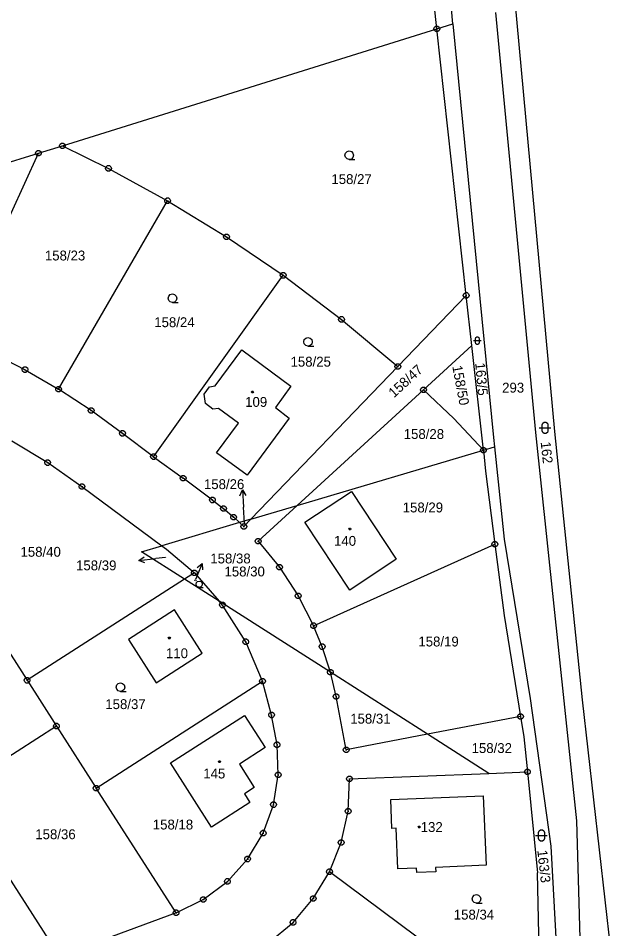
# Model space of a CAD drawing. Extents: x -780000 to -777378, y -1011169 to -1009297.
# Drawn here: x -779316 to -779212.2, y -1010124.6 to -1009967.9 of the extents above; entities that cross this region are included whole.
import ezdxf

# ---------------------------------------------------------------- set-up
doc = ezdxf.new("R2010")
doc.units = 0
for name, color, linetype in [('Default', 7, 'Continuous'), ('KN_HRANICE', 7, 'Continuous'), ('KN_KULTURY', 7, 'Continuous'), ('KN_PARCELY', 7, 'Continuous')]:
    doc.layers.add(name, color=color, linetype=linetype)

# ---------------------------------------------------------------- blocks, each defined once
blk = doc.blocks.new('304')
at = {"layer": 'Default'}
blk.add_lwpolyline([(0, 0), (-0.38, 0.1), (-0.65, 0.37), (-0.75, 0.74), (-0.65, 1.11), (-0.38, 1.38), (-0.01, 1.48), (0.36, 1.38), (0.63, 1.11), (0.73, 0.73), (0.63, 0.35), (0.36, 0.08), (-0.02, -0.02), (0.98, -0.02)], dxfattribs=at)
blk = doc.blocks.new('316')
at = {"layer": 'Default'}
for points in [[(-0.5, 1.5), (-0.4, 1.79), (-0.15, 1.97), (0.16, 1.97), (0.41, 1.79), (0.51, 1.5), (0.51, 0.5), (0.41, 0.21), (0.16, 0.03), (-0.15, 0.03), (-0.4, 0.21), (-0.5, 0.5), (-0.5, 1.5)], [(-1, 1), (0.27, 1), (1, 1)]]:
    blk.add_lwpolyline(points, dxfattribs=at)
blk = doc.blocks.new('10292')
at = {"layer": 'Default'}
blk.add_line((0, 3), (0, 0), dxfattribs=at)
blk.add_lwpolyline([(-0.5, 2), (0, 3), (0.5, 2)], dxfattribs=at)
blk = doc.blocks.new('105')
at = {"layer": 'Default'}
blk.add_line((-0.12, 0), (0.12, 0), dxfattribs=at)
blk.add_lwpolyline([(0.15, 0.48), (0.4, 0.3), (0.5, 0.01), (0.4, -0.28), (0.15, -0.46), (-0.16, -0.46), (-0.41, -0.28), (-0.51, 0.01), (-0.41, 0.3), (-0.16, 0.48), (0.15, 0.48)], dxfattribs=at)
blk = doc.blocks.new('402')
at = {"layer": 'Default'}
blk.add_lwpolyline([(0.09, 0.15), (0.18, 0), (0.09, -0.15), (-0.09, -0.15), (-0.18, 0), (-0.09, 0.15), (0.09, 0.15)], dxfattribs=at)

msp = doc.modelspace()

# ---------------------------------------------------------------- linework, layer by layer
at = {"layer": 'KN_HRANICE'}
for p, q in [((-779241.08, -1009968.91), (-779246.23, -1009913.12)), ((-779234.8, -1009917.25), (-779223.59, -1010039.03)), ((-779243.85, -1009969.77), (-779249.52, -1009918.58)), ((-779226.79, -1010039.25), (-779233.71, -1009966.95)), ((-779243.85, -1009969.77), (-779241.08, -1009968.91)), ((-779241.08, -1009968.91), (-779234.07, -1010040.11)), ((-779308.35, -1009989.9), (-779243.85, -1009969.77)), ((-779238.78, -1010015.64), (-779243.85, -1009969.77)), ((-779340.12, -1009999.61), (-779312.49, -1009991.16)), ((-779326.85, -1010022.6), (-779312.49, -1009991.16)), ((-779312.49, -1009991.16), (-779308.35, -1009989.9)), ((-779308.35, -1009989.9), (-779300.4, -1009993.78)), ((-779300.4, -1009993.78), (-779290.22, -1009999.35)), ((-779309, -1010031.79), (-779290.22, -1009999.35)), ((-779290.22, -1009999.35), (-779280.07, -1010005.56)), ((-779280.07, -1010005.56), (-779270.32, -1010012.18)), ((-779292.64, -1010043.39), (-779270.32, -1010012.18)), ((-779270.32, -1010012.18), (-779260.26, -1010019.77)), ((-779238.78, -1010015.64), (-779250.57, -1010027.88)), ((-779237.83, -1010024.25), (-779238.78, -1010015.64)), ((-779260.26, -1010019.77), (-779250.57, -1010027.88)), ((-779320.74, -1010025.36), (-779314.79, -1010028.42)), ((-779282.06, -1010031.21), (-779277.45, -1010024.98)), ((-779277.45, -1010024.98), (-779268.99, -1010031.25)), ((-779246.15, -1010031.88), (-779237.83, -1010024.25)), ((-779235.83, -1010042.28), (-779237.83, -1010024.25)), ((-779314.79, -1010028.42), (-779309, -1010031.79)), ((-779275.87, -1010054.16), (-779250.57, -1010027.88)), ((-779303.4, -1010035.47), (-779309, -1010031.79)), ((-779283.96, -1010032.63), (-779283.04, -1010031.37)), ((-779283.04, -1010031.37), (-779282.06, -1010031.21)), ((-779268.99, -1010031.25), (-779271.67, -1010034.94)), ((-779246.15, -1010031.88), (-779267.94, -1010051.81)), ((-779240.94, -1010036.84), (-779246.15, -1010031.88)), ((-779283.73, -1010034.23), (-779283.96, -1010032.63)), ((-779282.46, -1010035.19), (-779283.73, -1010034.23)), ((-779281.44, -1010035.08), (-779282.46, -1010035.19)), ((-779278, -1010037.62), (-779281.44, -1010035.08)), ((-779271.67, -1010034.94), (-779269.29, -1010036.77)), ((-779298.01, -1010039.38), (-779303.4, -1010035.47)), ((-779281.78, -1010042.74), (-779278, -1010037.62)), ((-779269.29, -1010036.77), (-779276.53, -1010046.6)), ((-779235.83, -1010042.28), (-779240.94, -1010036.84)), ((-779292.64, -1010043.39), (-779298.01, -1010039.38)), ((-779219.75, -1010106.05), (-779226.79, -1010039.25)), ((-779223.59, -1010039.03), (-779218.82, -1010085.26)), ((-779317.04, -1010040.66), (-779310.89, -1010044.42)), ((-779234.07, -1010040.11), (-779233.9, -1010041.71)), ((-779276.53, -1010046.6), (-779281.78, -1010042.74)), ((-779267.94, -1010051.81), (-779235.83, -1010042.28)), ((-779235.83, -1010042.28), (-779233.9, -1010041.71)), ((-779235.83, -1010042.28), (-779235.48, -1010045.87)), ((-779233.9, -1010041.71), (-779232.26, -1010057.56)), ((-779310.89, -1010044.42), (-779304.98, -1010048.53)), ((-779292.64, -1010043.39), (-779287.56, -1010047.11)), ((-779235.48, -1010045.87), (-779233.85, -1010058.45)), ((-779282.51, -1010050.85), (-779287.56, -1010047.11)), ((-779304.98, -1010048.53), (-779291.21, -1010058.71)), ((-779266.57, -1010054.66), (-779258.57, -1010049.37)), ((-779258.57, -1010049.37), (-779250.85, -1010061.04)), ((-779282.51, -1010050.85), (-779280.61, -1010052.33)), ((-779280.61, -1010052.33), (-779278.85, -1010053.8)), ((-779275.87, -1010054.16), (-779267.94, -1010051.81)), ((-779274.64, -1010057.94), (-779267.94, -1010051.81)), ((-779278.85, -1010053.8), (-779277.83, -1010054.74)), ((-779277.83, -1010054.74), (-779291.21, -1010058.71)), ((-779275.87, -1010054.16), (-779277.83, -1010054.74)), ((-779277.83, -1010054.74), (-779277.09, -1010055.43)), ((-779277.09, -1010055.43), (-779275.87, -1010054.16)), ((-779258.86, -1010066.35), (-779266.57, -1010054.66)), ((-779274.64, -1010057.94), (-779270.95, -1010062.42)), ((-779265.07, -1010072.49), (-779233.85, -1010058.45)), ((-779233.85, -1010058.45), (-779232.26, -1010070.73)), ((-779232.26, -1010057.56), (-779227.75, -1010085.02)), ((-779329.26, -1010058.8), (-779314.44, -1010081.88)), ((-779294.7, -1010059.75), (-779291.21, -1010058.71)), ((-779287.31, -1010064.46), (-779294.7, -1010059.75)), ((-779291.21, -1010058.71), (-779290.44, -1010059.28)), ((-779290.44, -1010059.28), (-779285.62, -1010063.38)), ((-779250.85, -1010061.04), (-779258.86, -1010066.35)), ((-779270.95, -1010062.42), (-779267.73, -1010067.35)), ((-779287.31, -1010064.46), (-779314.44, -1010081.88)), ((-779285.62, -1010063.38), (-779287.31, -1010064.46)), ((-779281.34, -1010068.27), (-779287.31, -1010064.46)), ((-779285.62, -1010063.38), (-779281.34, -1010068.27)), ((-779267.73, -1010067.35), (-779265.07, -1010072.49)), ((-779280.77, -1010068.92), (-779281.34, -1010068.27)), ((-779262.19, -1010080.48), (-779281.34, -1010068.27)), ((-779276.77, -1010075.24), (-779280.77, -1010068.92)), ((-779289.06, -1010069.75), (-779296.99, -1010074.85)), ((-779284.27, -1010077.21), (-779289.06, -1010069.75)), ((-779232.26, -1010070.73), (-779229.43, -1010088.1)), ((-779263.6, -1010076.09), (-779265.07, -1010072.49)), ((-779296.99, -1010074.85), (-779292.21, -1010082.32)), ((-779273.87, -1010082.04), (-779276.77, -1010075.24)), ((-779292.21, -1010082.32), (-779284.27, -1010077.21)), ((-779262.23, -1010080.33), (-779263.6, -1010076.09)), ((-779262.19, -1010080.48), (-779262.23, -1010080.33)), ((-779245.44, -1010091.17), (-779262.19, -1010080.48)), ((-779261.21, -1010084.68), (-779262.19, -1010080.48)), ((-779314.44, -1010081.88), (-779309.39, -1010089.76)), ((-779302.53, -1010100.44), (-779273.87, -1010082.04)), ((-779272.31, -1010087.85), (-779273.87, -1010082.04)), ((-779259.45, -1010093.86), (-779261.21, -1010084.68)), ((-779227.75, -1010085.02), (-779224.22, -1010110.43)), ((-779218.82, -1010085.26), (-779212.16, -1010143.8)), ((-779271.38, -1010092.97), (-779272.31, -1010087.85)), ((-779229.43, -1010088.1), (-779245.44, -1010091.17)), ((-779229.43, -1010088.1), (-779228.86, -1010091.61)), ((-779309.39, -1010089.76), (-779327.06, -1010101.1)), ((-779309.39, -1010089.76), (-779302.53, -1010100.44)), ((-779245.44, -1010091.17), (-779259.45, -1010093.86)), ((-779234.88, -1010097.91), (-779245.44, -1010091.17)), ((-779271.18, -1010098.16), (-779271.38, -1010092.97)), ((-779228.86, -1010091.61), (-779228.25, -1010097.65)), ((-779234.88, -1010097.91), (-779228.25, -1010097.65)), ((-779228.25, -1010097.65), (-779226.51, -1010114.99)), ((-779271.98, -1010103.28), (-779271.18, -1010098.16)), ((-779259.13, -1010104.42), (-779258.88, -1010098.83)), ((-779258.88, -1010098.83), (-779234.88, -1010097.91)), ((-779288.77, -1010121.88), (-779302.53, -1010100.44)), ((-779327.06, -1010101.1), (-779310.76, -1010126.49)), ((-779273.75, -1010108.17), (-779271.98, -1010103.28)), ((-779260.32, -1010109.8), (-779259.13, -1010104.42)), ((-779218.61, -1010144.17), (-779219.75, -1010106.05)), ((-779276.44, -1010112.63), (-779273.75, -1010108.17)), ((-779262.32, -1010114.82), (-779260.32, -1010109.8)), ((-779224.22, -1010110.43), (-779222.02, -1010149.91)), ((-779279.93, -1010116.49), (-779276.44, -1010112.63)), ((-779265.13, -1010119.44), (-779262.32, -1010114.82)), ((-779225.9, -1010141.96), (-779262.32, -1010114.82)), ((-779225.9, -1010141.96), (-779226.51, -1010114.99)), ((-779284.08, -1010119.61), (-779279.93, -1010116.49)), ((-779288.77, -1010121.88), (-779284.08, -1010119.61)), ((-779268.62, -1010123.54), (-779265.13, -1010119.44)), ((-779288.77, -1010121.88), (-779301.33, -1010126.54)), ((-779272.77, -1010127.01), (-779268.62, -1010123.54))]:
    msp.add_line(p, q, dxfattribs=at)
for points in [[(-779289.75, -1010096.1), (-779276.98, -1010087.91), (-779273.41, -1010093.44), (-779277.86, -1010096.28), (-779275.33, -1010100.31), (-779276.97, -1010101.4), (-779276.04, -1010102.9), (-779282.66, -1010107.15)], [(-779235.38, -1010113.69), (-779244.08, -1010114.07), (-779244.05, -1010114.82), (-779247.31, -1010114.94), (-779247.33, -1010114.19), (-779250.56, -1010114.32), (-779250.87, -1010107.34), (-779251.58, -1010107.36), (-779251.76, -1010102.41), (-779235.86, -1010101.78)]]:
    msp.add_lwpolyline(points, close=True, dxfattribs=at)
at = {"layer": 'KN_PARCELY'}
for p, q in [((-779276.99, -1010054.84), (-779277.15, -1010052.08)), ((-779290.6, -1010060.73), (-779292.23, -1010060.91)), ((-779285.55, -1010064.78), (-779285.44, -1010064.52))]:
    msp.add_line(p, q, dxfattribs=at)

# ---------------------------------------------------------------- block references
at = {"layer": 'KN_KULTURY'}
for name, p in [('304', (-779258.94, -1009992.24)), ('304', (-779289.39, -1010016.86)), ('304', (-779266.04, -1010024.35)), ('402', (-779275.61, -1010032.25)), ('316', (-779225.22, -1010039.43)), ('402', (-779258.82, -1010055.84)), ('402', (-779289.94, -1010074.61)), ('304', (-779298.35, -1010083.78)), ('402', (-779281.29, -1010095.89)), ('402', (-779246.89, -1010107.14)), ('316', (-779225.83, -1010109.58)), ('304', (-779237.02, -1010120.23))]:
    msp.add_blockref(name, p, dxfattribs=at)
for name, p, xscale, yscale in [('316', (-779236.88, -1010024.09), 0.67, 0.67), ('304', (-779284.79, -1010065.87), 0.72, 0.72)]:
    msp.add_blockref(name, p, dxfattribs=dict(at, xscale=xscale, yscale=yscale))
at = {"layer": 'KN_PARCELY'}
for p in [(-779243.85, -1009969.77), (-779308.35, -1009989.9), (-779312.49, -1009991.16), (-779300.4, -1009993.78), (-779290.22, -1009999.35), (-779280.07, -1010005.56), (-779270.32, -1010012.18), (-779238.78, -1010015.64), (-779260.26, -1010019.77), (-779314.79, -1010028.42), (-779250.57, -1010027.88), (-779309, -1010031.79), (-779246.15, -1010031.88), (-779303.4, -1010035.47), (-779298.01, -1010039.38), (-779292.64, -1010043.39), (-779235.83, -1010042.28), (-779310.89, -1010044.42), (-779287.56, -1010047.11), (-779304.98, -1010048.53), (-779282.51, -1010050.85), (-779280.61, -1010052.33), (-779278.85, -1010053.8), (-779277.09, -1010055.43), (-779274.64, -1010057.94), (-779233.85, -1010058.45), (-779285.62, -1010063.38), (-779270.95, -1010062.42), (-779267.73, -1010067.35), (-779280.77, -1010068.92), (-779265.07, -1010072.49), (-779276.77, -1010075.24), (-779263.6, -1010076.09), (-779262.19, -1010080.48), (-779314.44, -1010081.88), (-779273.87, -1010082.04), (-779261.21, -1010084.68), (-779272.31, -1010087.85), (-779229.43, -1010088.1), (-779309.39, -1010089.76), (-779271.38, -1010092.97), (-779259.45, -1010093.86), (-779271.18, -1010098.16), (-779228.25, -1010097.65), (-779258.88, -1010098.83), (-779302.53, -1010100.44), (-779271.98, -1010103.28), (-779259.13, -1010104.42), (-779273.75, -1010108.17), (-779260.32, -1010109.8), (-779276.44, -1010112.63), (-779262.32, -1010114.82), (-779279.93, -1010116.49), (-779284.08, -1010119.61), (-779265.13, -1010119.44), (-779288.77, -1010121.88), (-779268.62, -1010123.54)]:
    msp.add_blockref('105', p, dxfattribs=at)
for p, rotation in [((-779277.15, -1010052.08), 3.3804510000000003), ((-779292.23, -1010060.91), 96.42879699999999), ((-779285.44, -1010064.52), -23.158112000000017)]:
    msp.add_blockref('10292', p, dxfattribs=dict(at, rotation=rotation))

# ---------------------------------------------------------------- texts
for s, height, p in [('158/27', 1.7, (-779262.01, -1009996.47)), ('158/23', 1.7, (-779311.37, -1010009.62)), ('158/24', 1.7, (-779292.53, -1010021.1)), ('158/25', 1.7, (-779269.05, -1010027.89)), ('293', 1.7, (-779232.6, -1010032.36)), ('109', 1.7, (-779276.87, -1010034.82)), ('158/28', 1.7, (-779249.56, -1010040.34)), ('158/26', 1.7, (-779283.97, -1010048.97)), ('158/29', 1.7, (-779249.73, -1010052.98)), ('158/26', 0.1, (-779276.97, -1010054.84)), ('140', 1.7, (-779261.56, -1010058.73)), ('158/40', 1.7, (-779315.57, -1010060.61)), ('158/38', 1.7, (-779282.87, -1010061.76)), ('158/39', 1.7, (-779306, -1010062.95)), ('158/39', 0.1, (-779290.58, -1010060.73)), ('158/30', 1.7, (-779280.43, -1010064)), ('158/38', 0.1, (-779285.53, -1010064.78)), ('158/19', 1.7, (-779247.03, -1010076.05)), ('110', 1.7, (-779290.51, -1010078.07)), ('158/37', 1.7, (-779300.96, -1010086.83)), ('158/31', 1.7, (-779258.77, -1010089.33)), ('158/32', 1.7, (-779237.86, -1010094.39)), ('145', 1.7, (-779284.09, -1010098.77)), ('158/18', 1.7, (-779292.78, -1010107.55)), ('132', 1.7, (-779246.63, -1010107.98)), ('158/36', 1.7, (-779313.02, -1010109.22)), ('158/34', 1.7, (-779240.93, -1010123.05))]:
    msp.add_text(s, height=height, dxfattribs=at).set_placement(p)
for s, rotation, p in [('158/47', 42.456, (-779251.23, -1010033.34)), ('158/50', 280.635, (-779241.2, -1010027.84)), ('163/5', 275.077, (-779237.24, -1010027.28)), ('162', 276.338, (-779225.97, -1010040.89)), ('163/3', 276.395, (-779226.55, -1010111.16))]:
    msp.add_text(s, height=1.7, rotation=rotation, dxfattribs=at).set_placement(p)

doc.saveas('drawing.dxf')
